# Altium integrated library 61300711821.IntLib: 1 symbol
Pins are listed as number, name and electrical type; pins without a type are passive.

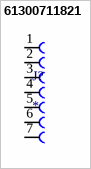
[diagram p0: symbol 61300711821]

## 61300711821
designator J?
Single Row / Straight / Without Shroud Female header Female 7 ¦ WÃ¼rth Elektronik 61300711821 @ Pin header, socket (Si...
footprint 61300711821
pins: 1, 2, 3, 4, 5, 6, 7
